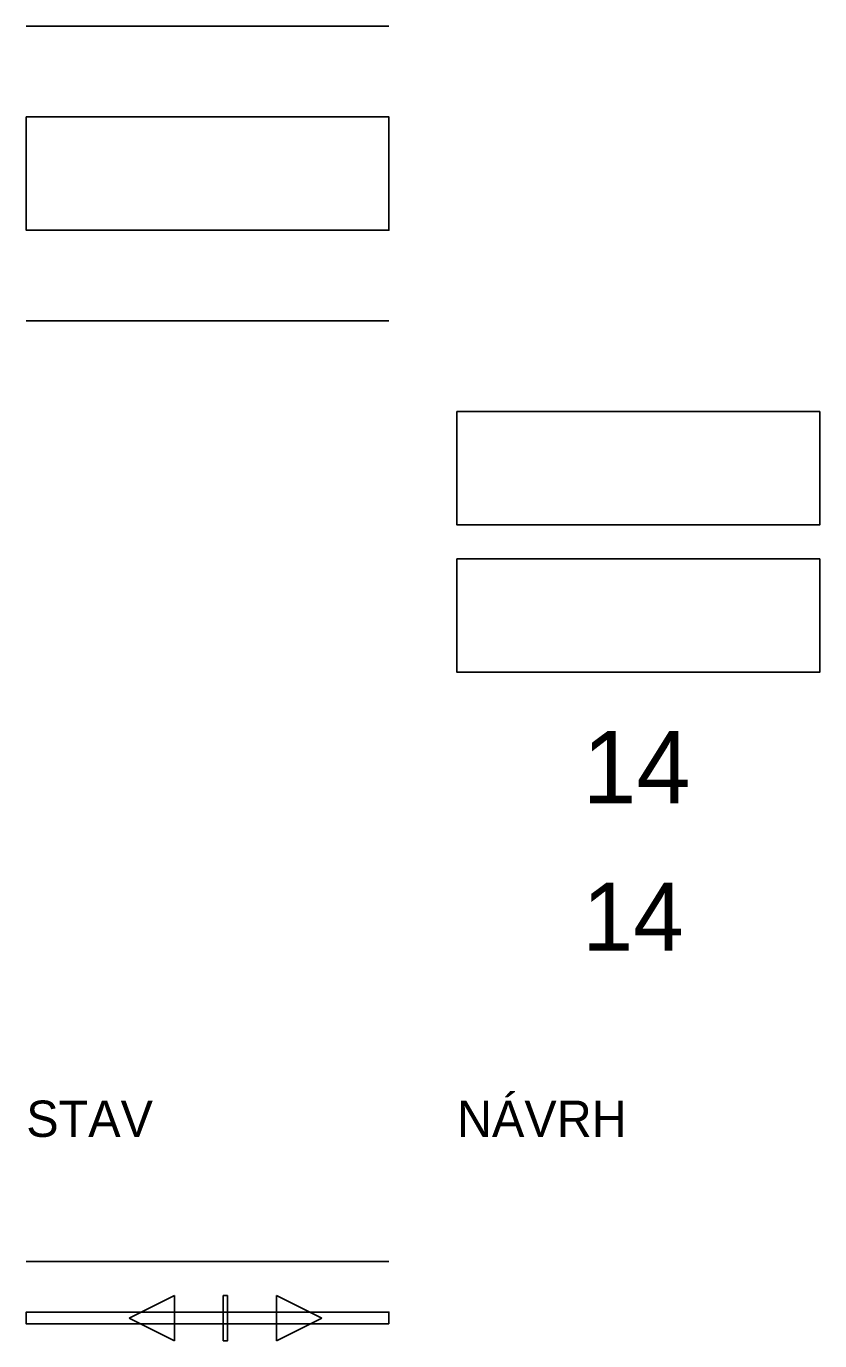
# Model space of a CAD drawing. Extents: x -477596 to -464945, y -1159281 to -1148316.
# Drawn here: x -467278 to -467103, y -1158340.9 to -1158050.9 of the extents above; entities that cross this region are included whole.
import ezdxf

# ---------------------------------------------------------------- set-up
doc = ezdxf.new("R2010")
doc.units = 0
for name, color, linetype in [('OP', 7, 'Continuous'), ('popis_plochy', 7, 'Continuous'), ('VN VZDUŠNÉ', 7, 'Continuous'), ('Vrstva 6', 7, 'Continuous'), ('Vrstva 60', 7, 'Continuous'), ('ZASTAVENE', 7, 'Continuous'), ('zemědělské_plochy', 7, 'Continuous')]:
    doc.layers.add(name, color=color, linetype=linetype)

msp = doc.modelspace()

# ---------------------------------------------------------------- linework, layer by layer
at = {"layer": 'OP'}
msp.add_line((-467277.96, -1158323.38), (-467197.96, -1158323.38), dxfattribs=at)
at = {"layer": 'VN VZDUŠNÉ'}
for p, q in [((-467245.3, -1158330.88), (-467255.3, -1158335.88)), ((-467245.3, -1158340.88), (-467245.3, -1158330.88)), ((-467222.8, -1158340.88), (-467222.8, -1158330.88)), ((-467222.8, -1158330.88), (-467212.8, -1158335.88)), ((-467255.3, -1158335.88), (-467245.3, -1158340.88)), ((-467212.8, -1158335.88), (-467222.8, -1158340.88))]:
    msp.add_line(p, q, dxfattribs=at)
for points in [[(-467233.55, -1158330.88), (-467233.55, -1158340.88), (-467234.55, -1158340.88)], [(-467234.55, -1158340.88), (-467234.55, -1158330.88)], [(-467234.55, -1158330.88), (-467233.55, -1158330.88)]]:
    msp.add_lwpolyline(points, dxfattribs=at)
msp.add_lwpolyline([(-467197.96, -1158337.18), (-467277.96, -1158337.18), (-467277.96, -1158334.58), (-467197.96, -1158334.58)], close=True, dxfattribs=at)
at = {"layer": 'Vrstva 6'}
msp.add_lwpolyline([(-467182.96, -1158168.42), (-467102.96, -1158168.42), (-467102.96, -1158193.42), (-467182.96, -1158193.42)], close=True, dxfattribs=at)
at = {"layer": 'ZASTAVENE'}
for points in [[(-467277.96, -1158070.92), (-467197.96, -1158070.92), (-467197.96, -1158095.92), (-467277.96, -1158095.92)], [(-467277.96, -1158070.92), (-467197.96, -1158070.92), (-467197.96, -1158095.92), (-467277.96, -1158095.92)], [(-467182.96, -1158135.92), (-467102.96, -1158135.92), (-467102.96, -1158160.92), (-467182.96, -1158160.92)]]:
    msp.add_lwpolyline(points, close=True, dxfattribs=at)
at = {"layer": 'zemědělské_plochy'}
for p, q in [((-467277.96, -1158050.92), (-467197.96, -1158050.92)), ((-467277.96, -1158115.92), (-467197.96, -1158115.92))]:
    msp.add_line(p, q, dxfattribs=at)

# ---------------------------------------------------------------- texts
at = {"layer": 'popis_plochy'}
for height, p in [(16, (-467155.26, -1158222.37)), (15, (-467155.26, -1158254.87))]:
    msp.add_text('14', height=height, dxfattribs=at).set_placement(p)
at = {"layer": 'Vrstva 60'}
for s, p in [('NÁVRH', (-467182.96, -1158295.91)), ('STAV', (-467277.96, -1158295.91))]:
    msp.add_text(s, height=8, dxfattribs=at).set_placement(p)

doc.saveas('drawing.dxf')
